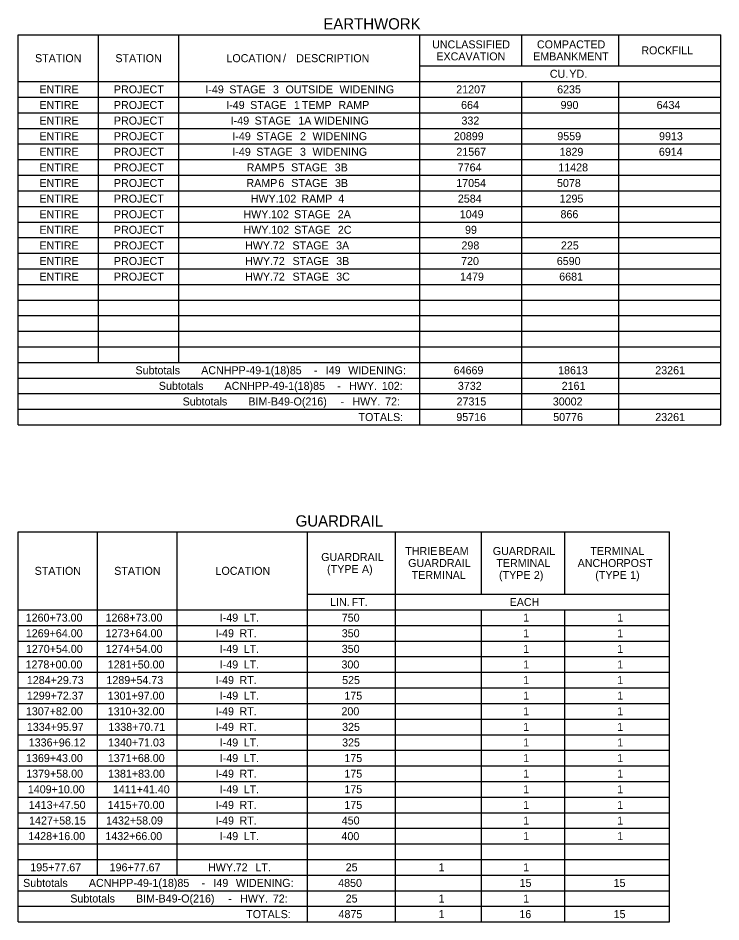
# Model space of a CAD drawing. Extents: x 1226605 to 1228152, y 151309 to 152316.
# Drawn here: x 1226605 to 1227044, y 151751 to 152316 of the extents above; entities that cross this region are included whole.
import ezdxf

# ---------------------------------------------------------------- set-up
doc = ezdxf.new("R2010")
doc.units = 0
doc.layers.add('R_Dimension', color=7, linetype='Continuous')

msp = doc.modelspace()

# ---------------------------------------------------------------- linework, layer by layer
at = {"layer": 'R_Dimension'}
for p, q in [((1226605.2, 152305.82), (1227044.44, 152305.82)), ((1226605.2, 152062.07), (1226605.2, 152305.82)), ((1226655.41, 152101.07), (1226655.41, 152305.82)), ((1226705.62, 152101.07), (1226705.62, 152305.82)), ((1226856.26, 152062.07), (1226856.26, 152305.82)), ((1226920.12, 152286.32), (1226920.12, 152305.82)), ((1226980.57, 152286.32), (1226980.57, 152305.82)), ((1227044.44, 152062.07), (1227044.44, 152305.82)), ((1226856.26, 152286.32), (1227044.44, 152286.32)), ((1226605.2, 152276.57), (1227044.44, 152276.57)), ((1226920.12, 152062.07), (1226920.12, 152276.57)), ((1226980.57, 152062.07), (1226980.57, 152276.57)), ((1226605.2, 152266.82), (1227044.44, 152266.82)), ((1226605.2, 152257.07), (1227044.44, 152257.07)), ((1226605.2, 152247.32), (1227044.44, 152247.32)), ((1226605.2, 152237.57), (1227044.44, 152237.57)), ((1226605.2, 152227.82), (1227044.44, 152227.82)), ((1226605.2, 152218.07), (1227044.44, 152218.07)), ((1226605.2, 152208.32), (1227044.44, 152208.32)), ((1226605.2, 152198.57), (1227044.44, 152198.57)), ((1226605.2, 152188.82), (1227044.44, 152188.82)), ((1226605.2, 152179.07), (1227044.44, 152179.07)), ((1226605.2, 152169.32), (1227044.44, 152169.32)), ((1226605.2, 152159.57), (1227044.44, 152159.57)), ((1226605.2, 152149.82), (1227044.44, 152149.82)), ((1226605.2, 152140.07), (1227044.44, 152140.07)), ((1226605.2, 152130.32), (1227044.44, 152130.32)), ((1226605.2, 152120.57), (1227044.44, 152120.57)), ((1226605.2, 152110.82), (1227044.44, 152110.82)), ((1226605.2, 152101.07), (1227044.44, 152101.07)), ((1226605.2, 152091.32), (1227044.44, 152091.32)), ((1226605.2, 152081.57), (1227044.44, 152081.57)), ((1226605.2, 152071.82), (1227044.44, 152071.82)), ((1226605.2, 152062.07), (1227044.44, 152062.07)), ((1226605.2, 151995.24), (1227012.26, 151995.24)), ((1226605.2, 151751.49), (1226605.2, 151995.24)), ((1226654.92, 151780.74), (1226654.92, 151995.24)), ((1226704.65, 151780.74), (1226704.65, 151995.24)), ((1226786.06, 151751.49), (1226786.06, 151995.24)), ((1226841.15, 151751.49), (1226841.15, 151995.24)), ((1226894.77, 151956.24), (1226894.77, 151995.24)), ((1226946.94, 151956.24), (1226946.94, 151995.24)), ((1227012.26, 151751.49), (1227012.26, 151995.24)), ((1226786.06, 151956.24), (1227012.26, 151956.24)), ((1226605.2, 151946.49), (1227012.26, 151946.49)), ((1226894.77, 151751.49), (1226894.77, 151946.49)), ((1226946.94, 151751.49), (1226946.94, 151946.49)), ((1226605.2, 151936.74), (1227012.26, 151936.74)), ((1226605.2, 151926.99), (1227012.26, 151926.99)), ((1226605.2, 151917.24), (1227012.26, 151917.24)), ((1226605.2, 151907.49), (1227012.26, 151907.49)), ((1226605.2, 151897.74), (1227012.26, 151897.74)), ((1226605.2, 151887.99), (1227012.26, 151887.99)), ((1226605.2, 151878.24), (1227012.26, 151878.24)), ((1226605.2, 151868.49), (1227012.26, 151868.49)), ((1226605.2, 151858.74), (1227012.26, 151858.74)), ((1226605.2, 151848.99), (1227012.26, 151848.99)), ((1226605.2, 151839.24), (1227012.26, 151839.24)), ((1226605.2, 151829.49), (1227012.26, 151829.49)), ((1226605.2, 151819.74), (1227012.26, 151819.74)), ((1226605.2, 151809.99), (1227012.26, 151809.99)), ((1226605.2, 151800.24), (1227012.26, 151800.24)), ((1226605.2, 151790.49), (1227012.26, 151790.49)), ((1226605.2, 151780.74), (1227012.26, 151780.74)), ((1226605.2, 151770.99), (1227012.26, 151770.99)), ((1226605.2, 151761.24), (1227012.26, 151761.24)), ((1226605.2, 151751.49), (1227012.26, 151751.49))]:
    msp.add_line(p, q, dxfattribs=at)

# ---------------------------------------------------------------- texts
for s, height, p in [('EARTHWORK', 7, (1226795.94, 152309.15)), ('UNCLASSIFIED', 5, (1226863.96, 152297.32)), ('COMPACTED', 5, (1226929.46, 152297.32)), ('EXCAVATION', 5, (1226866.6, 152289.82)), ('EMBANKMENT', 5, (1226927.1, 152289.82)), ('ROCK', 5, (1226994.69, 152293.57)), (' FILL', 5, (1227011.86, 152293.57)), ('STATION', 5, (1226615.8, 152288.7)), ('STATION', 5, (1226666.01, 152288.7)), ('LOCATION', 5, (1226735.41, 152288.7)), (' /', 5, (1226768.92, 152288.7)), (' DESCRIPTION', 5, (1226777.18, 152288.7)), ('CU.', 5, (1226937.53, 152278.95)), (' YD.', 5, (1226947.85, 152278.95)), ('ENTIRE', 5, (1226618.53, 152269.2)), ('PROJECT', 5, (1226665.07, 152269.2)), ('I-49', 5, (1226722.24, 152269.2)), (' STAGE', 5, (1226735.35, 152269.2)), (' 3', 5, (1226762.64, 152269.2)), (' OUTSIDE', 5, (1226770.47, 152269.2)), (' WIDENING', 5, (1226804.21, 152269.2)), ('21207', 5, (1226879.02, 152269.2)), ('6235', 5, (1226942.08, 152269.2)), ('ENTIRE', 5, (1226618.53, 152259.45)), ('PROJECT', 5, (1226665.07, 152259.45)), ('I-49', 5, (1226735.29, 152259.45)), (' STAGE', 5, (1226748.4, 152259.45)), (' 1', 5, (1226775.69, 152259.45)), (' TEMP', 5, (1226780.69, 152259.45)), (' RAMP', 5, (1226803.52, 152259.45)), ('664', 5, (1226882.05, 152259.45)), ('990', 5, (1226944.23, 152259.45)), ('6434', 5, (1227004.24, 152259.45)), ('ENTIRE', 5, (1226618.53, 152249.7)), ('PROJECT', 5, (1226665.07, 152249.7)), ('I-49', 5, (1226738.07, 152249.7)), (' STAGE', 5, (1226751.18, 152249.7)), (' 1A', 5, (1226778.46, 152249.7)), (' WIDENING', 5, (1226788.38, 152249.7)), ('332', 5, (1226882.29, 152249.7)), ('ENTIRE', 5, (1226618.53, 152239.95)), ('PROJECT', 5, (1226665.07, 152239.95)), ('I-49', 5, (1226739.11, 152239.95)), (' STAGE', 5, (1226752.22, 152239.95)), (' 2', 5, (1226779.51, 152239.95)), (' WIDENING', 5, (1226787.34, 152239.95)), ('20899', 5, (1226877.58, 152239.95)), ('9559', 5, (1226942.18, 152239.95)), ('9913', 5, (1227005.77, 152239.95)), ('ENTIRE', 5, (1226618.53, 152230.2)), ('PROJECT', 5, (1226665.07, 152230.2)), ('I-49', 5, (1226739.11, 152230.2)), (' STAGE', 5, (1226752.22, 152230.2)), (' 3', 5, (1226779.51, 152230.2)), (' WIDENING', 5, (1226787.34, 152230.2)), ('21567', 5, (1226879.1, 152230.2)), ('1829', 5, (1226943.6, 152230.2)), ('6914', 5, (1227005.66, 152230.2)), ('ENTIRE', 5, (1226618.53, 152220.45)), ('PROJECT', 5, (1226665.07, 152220.45)), ('RAMP', 5, (1226748.05, 152220.45)), (' 5', 5, (1226766.12, 152220.45)), (' STAGE', 5, (1226773.95, 152220.45)), (' 3B', 5, (1226801.24, 152220.45)), ('7764', 5, (1226879.93, 152220.45)), ('11428', 5, (1226942.79, 152220.45)), ('ENTIRE', 5, (1226618.53, 152210.7)), ('PROJECT', 5, (1226665.07, 152210.7)), ('RAMP', 5, (1226747.91, 152210.7)), (' 6', 5, (1226765.98, 152210.7)), (' STAGE', 5, (1226774.09, 152210.7)), (' 3B', 5, (1226801.38, 152210.7)), ('17054', 5, (1226879.02, 152210.7)), ('5078', 5, (1226942, 152210.7)), ('ENTIRE', 5, (1226618.53, 152200.95)), ('PROJECT', 5, (1226665.07, 152200.95)), ('HWY.', 5, (1226750.59, 152200.95)), (' 102', 5, (1226766.02, 152200.95)), (' RAMP', 5, (1226780.39, 152200.95)), (' 4', 5, (1226803.46, 152200.95)), ('2584', 5, (1226880.04, 152200.95)), ('1295', 5, (1226943.62, 152200.95)), ('ENTIRE', 5, (1226618.53, 152191.2)), ('PROJECT', 5, (1226665.07, 152191.2)), ('HWY.', 5, (1226746.02, 152191.2)), (' 102', 5, (1226761.45, 152191.2)), (' STAGE', 5, (1226775.82, 152191.2)), (' 2A', 5, (1226803.11, 152191.2)), ('1049', 5, (1226881.24, 152191.2)), ('866', 5, (1226944.19, 152191.2)), ('ENTIRE', 5, (1226618.53, 152181.45)), ('PROJECT', 5, (1226665.07, 152181.45)), ('HWY.', 5, (1226746.1, 152181.45)), (' 102', 5, (1226761.53, 152181.45)), (' STAGE', 5, (1226775.9, 152181.45)), (' 2C', 5, (1226803.19, 152181.45)), ('99', 5, (1226884.51, 152181.45)), ('ENTIRE', 5, (1226618.53, 152171.7)), ('PROJECT', 5, (1226665.07, 152171.7)), ('HWY.', 5, (1226747.05, 152171.7)), (' 72', 5, (1226762.48, 152171.7)), (' STAGE', 5, (1226774.8, 152171.7)), (' 3A', 5, (1226802.08, 152171.7)), ('298', 5, (1226882.29, 152171.7)), ('225', 5, (1226944.44, 152171.7)), ('ENTIRE', 5, (1226618.53, 152161.95)), ('PROJECT', 5, (1226665.07, 152161.95)), ('HWY.', 5, (1226747.12, 152161.95)), (' 72', 5, (1226762.56, 152161.95)), (' STAGE', 5, (1226774.88, 152161.95)), (' 3B', 5, (1226802.16, 152161.95)), ('720', 5, (1226882.07, 152161.95)), ('6590', 5, (1226941.87, 152161.95)), ('ENTIRE', 5, (1226618.53, 152152.2)), ('PROJECT', 5, (1226665.07, 152152.2)), ('HWY.', 5, (1226747.12, 152152.2)), (' 72', 5, (1226762.56, 152152.2)), (' STAGE', 5, (1226774.88, 152152.2)), (' 3C', 5, (1226802.16, 152152.2)), ('1479', 5, (1226881.44, 152152.2)), ('6681', 5, (1226943.38, 152152.2)), ('Subtotals', 5, (1226678.55, 152093.7)), (' ACNHPP-49-1(18)85', 5, (1226717.76, 152093.7)), (' I49', 5, (1226795.64, 152093.7)), (' WIDENING:', 5, (1226809.65, 152093.7)), ('64669', 5, (1226877.43, 152093.7)), ('18613', 5, (1226942.67, 152093.7)), ('23261', 5, (1227003.41, 152093.7)), (' -', 5, (1226788.2, 152093.7)), ('Subtotals', 5, (1226693.16, 152083.95)), (' ACNHPP-49-1(18)85', 5, (1226732.37, 152083.95)), (' -', 5, (1226802.8, 152083.95)), (' HWY.', 5, (1226810.24, 152083.95)), (' 102:', 5, (1226830.68, 152083.95)), ('3732', 5, (1226880.04, 152083.95)), ('2161', 5, (1226944.92, 152083.95)), ('Subtotals', 5, (1226708.04, 152074.2)), (' BIM-B49-O(216)', 5, (1226747.25, 152074.2)), (' -', 5, (1226804.85, 152074.2)), (' HWY.', 5, (1226812.29, 152074.2)), (' 72:', 5, (1226832.72, 152074.2)), ('27315', 5, (1226879.22, 152074.2)), ('30002', 5, (1226939.37, 152074.2)), ('TOTALS:', 5, (1226817.96, 152064.45)), ('95716', 5, (1226879.08, 152064.45)), ('50776', 5, (1226939.62, 152064.45)), ('23261', 5, (1227003.41, 152064.45)), ('GUARDRAIL', 7, (1226778.66, 151998.56)), ('THRIE', 5, (1226847.15, 151980.74)), (' BEAM', 5, (1226865.97, 151980.74)), ('GUARDRAIL', 5, (1226901.88, 151980.74)), ('TERMINAL', 5, (1226962.83, 151980.74)), ('GUARDRAIL', 5, (1226794.63, 151976.99)), ('GUARDRAIL', 5, (1226848.99, 151973.24)), ('TERMINAL', 5, (1226904.08, 151973.24)), ('ANCHOR', 5, (1226954.89, 151973.24)), (' POST', 5, (1226981.71, 151973.24)), ('STATION', 5, (1226615.55, 151968.36)), ('STATION', 5, (1226665.28, 151968.36)), ('LOCATION', 5, (1226728.6, 151968.36)), ('(TYPE', 5, (1226798.31, 151969.49)), (' A)', 5, (1226818.23, 151969.49)), ('TERMINAL', 5, (1226851.19, 151965.74)), ('(TYPE', 5, (1226905.76, 151965.74)), (' 2)', 5, (1226925.68, 151965.74)), ('(TYPE', 5, (1226965.92, 151965.74)), (' 1)', 5, (1226985.84, 151965.74)), ('LIN.', 5, (1226800.2, 151948.86)), (' FT.', 5, (1226811.85, 151948.86)), ('EACH', 5, (1226912.39, 151948.86)), ('1260+73.00', 5, (1226609.96, 151939.11)), ('1268+73.00', 5, (1226659.89, 151939.11)), ('I-49', 5, (1226731.22, 151939.11)), (' LT.', 5, (1226744.33, 151939.11)), ('750', 5, (1226807.48, 151939.11)), ('1', 5, (1226920.86, 151939.11)), ('1', 5, (1226979.6, 151939.11)), ('1269+64.00', 5, (1226610.04, 151929.36)), ('1273+64.00', 5, (1226659.89, 151929.36)), ('I-49', 5, (1226728.6, 151929.36)), (' RT.', 5, (1226741.71, 151929.36)), ('350', 5, (1226807.48, 151929.36)), ('1', 5, (1226920.86, 151929.36)), ('1', 5, (1226979.6, 151929.36)), ('1270+54.00', 5, (1226610.08, 151919.61)), ('1274+54.00', 5, (1226660, 151919.61)), ('I-49', 5, (1226731.22, 151919.61)), (' LT.', 5, (1226744.33, 151919.61)), ('350', 5, (1226807.48, 151919.61)), ('1', 5, (1226920.86, 151919.61)), ('1', 5, (1226979.6, 151919.61)), ('1278+00.00', 5, (1226609.88, 151909.86)), ('1281+50.00', 5, (1226661.22, 151909.86)), ('I-49', 5, (1226731.22, 151909.86)), (' LT.', 5, (1226744.33, 151909.86)), ('300', 5, (1226807.29, 151909.86)), ('1', 5, (1226920.86, 151909.86)), ('1', 5, (1226979.6, 151909.86)), ('1284+29.73', 5, (1226610.69, 151900.11)), ('1289+54.73', 5, (1226660.42, 151900.11)), ('I-49', 5, (1226728.6, 151900.11)), (' RT.', 5, (1226741.71, 151900.11)), ('525', 5, (1226807.7, 151900.11)), ('1', 5, (1226920.86, 151900.11)), ('1', 5, (1226979.6, 151900.11)), ('1299+72.37', 5, (1226610.69, 151890.36)), ('1301+97.00', 5, (1226661.22, 151890.36)), ('I-49', 5, (1226731.22, 151890.36)), (' LT.', 5, (1226744.33, 151890.36)), ('175', 5, (1226809.12, 151890.36)), ('1', 5, (1226920.86, 151890.36)), ('1', 5, (1226979.6, 151890.36)), ('1307+82.00', 5, (1226610.08, 151880.61)), ('1310+32.00', 5, (1226661.22, 151880.61)), ('I-49', 5, (1226728.6, 151880.61)), (' RT.', 5, (1226741.71, 151880.61)), ('200', 5, (1226807.29, 151880.61)), ('1', 5, (1226920.86, 151880.61)), ('1', 5, (1226979.6, 151880.61)), ('1334+95.97', 5, (1226610.69, 151870.86)), ('1338+70.71', 5, (1226661.64, 151870.86)), ('I-49', 5, (1226728.6, 151870.86)), (' RT.', 5, (1226741.71, 151870.86)), ('325', 5, (1226807.7, 151870.86)), ('1', 5, (1226920.86, 151870.86)), ('1', 5, (1226979.6, 151870.86)), ('1336+96.12', 5, (1226611.87, 151861.11)), ('1340+71.03', 5, (1226661.44, 151861.11)), ('I-49', 5, (1226731.22, 151861.11)), (' LT.', 5, (1226744.33, 151861.11)), ('325', 5, (1226807.7, 151861.11)), ('1', 5, (1226920.86, 151861.11)), ('1', 5, (1226979.6, 151861.11)), ('1369+43.00', 5, (1226610.16, 151851.36)), ('1371+68.00', 5, (1226661.3, 151851.36)), ('I-49', 5, (1226731.22, 151851.36)), (' LT.', 5, (1226744.33, 151851.36)), ('175', 5, (1226809.12, 151851.36)), ('1', 5, (1226920.86, 151851.36)), ('1', 5, (1226979.6, 151851.36)), ('1379+58.00', 5, (1226610.28, 151841.61)), ('1381+83.00', 5, (1226661.42, 151841.61)), ('I-49', 5, (1226728.6, 151841.61)), (' RT.', 5, (1226741.71, 151841.61)), ('175', 5, (1226809.12, 151841.61)), ('1', 5, (1226920.86, 151841.61)), ('1', 5, (1226979.6, 151841.61)), ('1409+10.00', 5, (1226611.3, 151831.86)), ('1411+41.40', 5, (1226664.45, 151831.86)), ('I-49', 5, (1226731.22, 151831.86)), (' LT.', 5, (1226744.33, 151831.86)), ('175', 5, (1226809.12, 151831.86)), ('1', 5, (1226920.86, 151831.86)), ('1', 5, (1226979.6, 151831.86)), ('1413+47.50', 5, (1226611.89, 151822.11)), ('1415+70.00', 5, (1226661.22, 151822.11)), ('I-49', 5, (1226728.6, 151822.11)), (' RT.', 5, (1226741.71, 151822.11)), ('175', 5, (1226809.12, 151822.11)), ('1', 5, (1226920.86, 151822.11)), ('1', 5, (1226979.6, 151822.11)), ('1427+58.15', 5, (1226612.11, 151812.36)), ('1432+58.09', 5, (1226660.2, 151812.36)), ('I-49', 5, (1226728.6, 151812.36)), (' RT.', 5, (1226741.71, 151812.36)), ('450', 5, (1226807.48, 151812.36)), ('1', 5, (1226920.86, 151812.36)), ('1', 5, (1226979.6, 151812.36)), ('1428+16.00', 5, (1226611.58, 151802.61)), ('1432+66.00', 5, (1226659.77, 151802.61)), ('I-49', 5, (1226731.22, 151802.61)), (' LT.', 5, (1226744.33, 151802.61)), ('400', 5, (1226807.29, 151802.61)), ('1', 5, (1226920.86, 151802.61)), ('1', 5, (1226979.6, 151802.61)), ('195+77.67', 5, (1226612.82, 151783.11)), ('196+77.67', 5, (1226662.42, 151783.11)), ('HWY.', 5, (1226723.9, 151783.11)), (' 72', 5, (1226739.33, 151783.11)), (' LT.', 5, (1226751.65, 151783.11)), ('25', 5, (1226809.94, 151783.11)), ('1', 5, (1226867.96, 151783.11)), ('1', 5, (1226920.86, 151783.11)), ('Subtotals', 5, (1226608.35, 151773.36)), (' ACNHPP-49-1(18)85', 5, (1226647.56, 151773.36)), (' -', 5, (1226718, 151773.36)), (' I49', 5, (1226725.44, 151773.36)), (' WIDENING:', 5, (1226739.45, 151773.36)), ('4850', 5, (1226805.24, 151773.36)), ('15', 5, (1226918.61, 151773.36)), ('15', 5, (1226977.36, 151773.36)), ('Subtotals', 5, (1226637.84, 151763.61)), (' BIM-B49-O(216)', 5, (1226677.05, 151763.61)), (' -', 5, (1226734.65, 151763.61)), (' HWY.', 5, (1226742.09, 151763.61)), (' 72:', 5, (1226762.52, 151763.61)), ('25', 5, (1226809.94, 151763.61)), ('1', 5, (1226867.96, 151763.61)), ('1', 5, (1226920.86, 151763.61)), ('TOTALS:', 5, (1226747.76, 151753.86)), ('4875', 5, (1226805.46, 151753.86)), ('1', 5, (1226867.96, 151753.86)), ('16', 5, (1226918.47, 151753.86)), ('15', 5, (1226977.36, 151753.86))]:
    msp.add_text(s, height=height, dxfattribs=at).set_placement(p)

doc.saveas('drawing.dxf')
